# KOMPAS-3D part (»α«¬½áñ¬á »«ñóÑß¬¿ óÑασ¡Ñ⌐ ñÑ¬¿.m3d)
File: created 05.09.2015 19:47:00, last saved 22.07.2016 14:57:03.
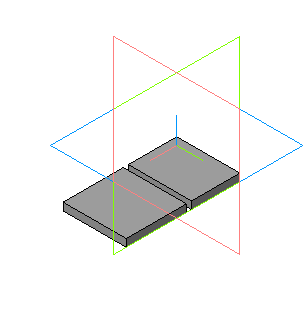
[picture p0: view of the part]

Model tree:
1. Эскиз:1
2. Операция выдавливания:1
     Расстояние 1 = 3
3. Эскиз:2
4. Вырезать элемент выдавливания:1
     Толщина стенки 1 = 2; Расстояние 1 = 10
